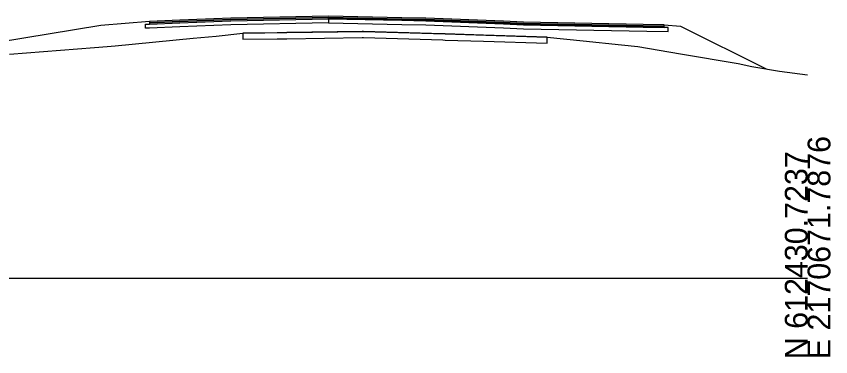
# Model space of a CAD drawing. Extents: x -26 to 1303, y -3010 to 12038.
# Drawn here: x 202.7 to 302.8, y 9490.3 to 9532.2 of the extents above; entities that cross this region are included whole.
import ezdxf

# ---------------------------------------------------------------- set-up
doc = ezdxf.new("R2010")
doc.units = 0
for name, color, linetype in [('RD_GPK_XS_Cell', 7, 'Continuous'), ('RD_XS_Base', 7, 'Continuous'), ('RD_XS_ExGround', 7, 'Continuous'), ('RD_XS_ExPaveRet', 7, 'Continuous'), ('RD_XS_Greenside', 7, 'Continuous'), ('RD_XS_Pave', 7, 'Continuous'), ('RD_XS_PaveOvlay_CP', 7, 'Continuous'), ('RD_XS_TieSlope', 7, 'Continuous')]:
    doc.layers.add(name, color=color, linetype=linetype)

msp = doc.modelspace()

# ---------------------------------------------------------------- linework, layer by layer
at = {"layer": 'RD_GPK_XS_Cell'}
msp.add_line((150, 9500), (300, 9500), dxfattribs=at)
at = {"layer": 'RD_XS_Base'}
for p, q in [((241.06, 9531.96), (241.06, 9532.07)), ((241.06, 9532.07), (241.06, 9531.59)), ((218.56, 9531.25), (218.75, 9531.26)), ((218.56, 9530.94), (218.56, 9531.25)), ((218.75, 9531.26), (219.06, 9531.27)), ((219.06, 9531.27), (222.79, 9531.42)), ((222.79, 9531.42), (229.06, 9531.67)), ((229.06, 9531.17), (222.79, 9530.92)), ((229.06, 9531.67), (241.06, 9531.91)), ((241.06, 9531.41), (229.06, 9531.17)), ((241.06, 9531.91), (241.06, 9531.96)), ((241.06, 9531.91), (241.06, 9531.91)), ((250.11, 9531.73), (241.06, 9531.91)), ((241.06, 9531.91), (241.06, 9531.91)), ((241.06, 9531.91), (241.06, 9531.55)), ((241.06, 9531.59), (241.06, 9531.41)), ((241.06, 9531.55), (241.06, 9531.41)), ((241.06, 9531.41), (250.11, 9531.23)), ((253.06, 9531.67), (250.11, 9531.73)), ((250.11, 9531.23), (253.06, 9531.17)), ((262.6, 9531.29), (253.06, 9531.67)), ((253.06, 9531.17), (262.6, 9530.79)), ((265.06, 9531.19), (262.6, 9531.29)), ((279.76, 9530.9), (265.06, 9531.19)), ((218.56, 9530.75), (218.56, 9530.94)), ((218.75, 9530.76), (218.56, 9530.75)), ((219.06, 9530.77), (218.75, 9530.76)), ((222.79, 9530.92), (219.06, 9530.77)), ((262.6, 9530.79), (265.06, 9530.69)), ((265.06, 9530.69), (280.21, 9530.39)), ((282.36, 9530.85), (279.76, 9530.9)), ((280.21, 9530.39), (282.86, 9530.34)), ((282.79, 9530.84), (282.36, 9530.85)), ((282.86, 9530.84), (282.79, 9530.84)), ((282.86, 9530.41), (282.86, 9530.84)), ((282.86, 9530.34), (282.86, 9530.41))]:
    msp.add_line(p, q, dxfattribs=at)
at = {"layer": 'RD_XS_ExGround'}
msp.add_lwpolyline([(201.83, 9527.58), (212.32, 9528.37), (213.87, 9528.49), (214.83, 9528.59), (224.44, 9529.53), (227.26, 9529.79), (230.55, 9530.14), (235.96, 9530.22), (245.39, 9530.36), (255.43, 9530.05), (267.97, 9529.67), (272.39, 9529.21), (277.13, 9528.7), (279.11, 9528.49), (284.36, 9527.59), (291.45, 9526.43), (293.12, 9526.03), (296.53, 9525.46), (300, 9525)], dxfattribs=at)
at = {"layer": 'RD_XS_ExPaveRet'}
for p, q in [((260.14, 9529.91), (255.43, 9530.05)), ((267.97, 9529.67), (260.14, 9529.91))]:
    msp.add_line(p, q, dxfattribs=at)
for points in [[(260.14, 9529.91), (255.43, 9530.05), (255.13, 9530.06), (245.39, 9530.36), (245.21, 9530.36), (235.96, 9530.22), (234.76, 9530.2), (230.55, 9530.14), (230.55, 9530.05), (230.55, 9529.39), (234.76, 9529.45), (235.96, 9529.47), (245.21, 9529.61), (245.39, 9529.61), (255.13, 9529.31), (255.43, 9529.3), (260.14, 9529.16), (267.97, 9528.92), (267.97, 9529.64), (267.97, 9529.67), (260.14, 9529.91)], [(235.96, 9530.22), (234.76, 9530.2), (230.55, 9530.14)], [(230.55, 9530.14), (230.55, 9530.05), (230.55, 9529.39), (234.76, 9529.45), (235.96, 9529.47), (245.21, 9529.61), (245.39, 9529.61), (255.13, 9529.31), (255.43, 9529.3), (260.14, 9529.16), (267.97, 9528.92), (267.97, 9529.64), (267.97, 9529.67)], [(255.43, 9530.05), (255.13, 9530.06), (245.39, 9530.36), (245.21, 9530.36), (235.96, 9530.22)]]:
    msp.add_lwpolyline(points, dxfattribs=at)
at = {"layer": 'RD_XS_Greenside'}
for p, q in [((213.06, 9531.11), (194.49, 9528.01)), ((284.36, 9531), (294.9, 9525.74))]:
    msp.add_line(p, q, dxfattribs=at)
at = {"layer": 'RD_XS_Pave'}
for p, q in [((229.06, 9531.99), (222.79, 9531.74)), ((241.06, 9532.23), (229.06, 9531.99)), ((241.06, 9532.07), (229.06, 9531.83)), ((229.06, 9531.83), (241.06, 9532.07)), ((250.11, 9532.05), (241.06, 9532.23)), ((241.06, 9531.96), (241.06, 9532.07)), ((241.06, 9532.07), (250.11, 9531.89)), ((250.11, 9531.89), (241.06, 9532.07)), ((241.06, 9532.07), (241.06, 9532.07)), ((241.06, 9532.07), (241.06, 9532.07)), ((241.06, 9532.07), (241.06, 9531.96)), ((253.06, 9531.99), (250.11, 9532.05)), ((262.6, 9531.61), (253.06, 9531.99)), ((222.79, 9531.74), (219.06, 9531.59)), ((219.06, 9531.59), (219.06, 9531.49)), ((222.79, 9531.58), (219.06, 9531.43)), ((219.06, 9531.43), (222.79, 9531.58)), ((219.06, 9531.49), (219.06, 9531.43)), ((219.06, 9531.43), (219.06, 9531.33)), ((219.06, 9531.27), (222.79, 9531.42)), ((219.06, 9531.33), (219.06, 9531.27)), ((229.06, 9531.83), (222.79, 9531.58)), ((222.79, 9531.58), (229.06, 9531.83)), ((222.79, 9531.42), (229.06, 9531.67)), ((229.06, 9531.67), (241.06, 9531.91)), ((241.06, 9531.91), (241.06, 9531.96)), ((241.06, 9531.96), (241.06, 9531.91)), ((241.06, 9531.91), (241.06, 9531.91)), ((241.06, 9531.91), (241.06, 9531.91)), ((241.06, 9531.91), (250.11, 9531.73)), ((250.11, 9531.89), (253.06, 9531.83)), ((253.06, 9531.83), (250.11, 9531.89)), ((250.11, 9531.73), (253.06, 9531.67)), ((253.06, 9531.83), (262.6, 9531.45)), ((262.6, 9531.45), (253.06, 9531.83)), ((253.06, 9531.67), (262.6, 9531.29)), ((265.06, 9531.51), (262.6, 9531.61)), ((262.6, 9531.45), (265.06, 9531.35)), ((265.06, 9531.35), (262.6, 9531.45)), ((262.6, 9531.29), (265.06, 9531.19)), ((279.76, 9531.22), (265.06, 9531.51)), ((265.06, 9531.35), (279.76, 9531.06)), ((279.76, 9531.06), (265.06, 9531.35)), ((265.06, 9531.19), (279.76, 9530.9)), ((282.36, 9531.16), (279.76, 9531.22)), ((279.76, 9531.06), (282.36, 9531)), ((282.36, 9531), (279.76, 9531.06)), ((282.36, 9531.03), (282.36, 9531.16)), ((282.36, 9531), (282.36, 9531.03)), ((282.36, 9530.87), (282.36, 9531)), ((279.76, 9530.9), (282.36, 9530.85)), ((282.36, 9530.85), (282.36, 9530.87))]:
    msp.add_line(p, q, dxfattribs=at)
at = {"layer": 'RD_XS_PaveOvlay_CP'}
for p, q in [((229.06, 9531.99), (222.79, 9531.74)), ((241.06, 9532.23), (229.06, 9531.99)), ((250.11, 9532.05), (241.06, 9532.23)), ((253.06, 9531.99), (250.11, 9532.05)), ((262.6, 9531.61), (253.06, 9531.99)), ((222.79, 9531.74), (219.06, 9531.59)), ((265.06, 9531.51), (262.6, 9531.61)), ((279.76, 9531.22), (265.06, 9531.51)), ((282.36, 9531.16), (279.76, 9531.22))]:
    msp.add_line(p, q, dxfattribs=at)
at = {"layer": 'RD_XS_TieSlope'}
for p, q in [((219.06, 9531.59), (213.06, 9531.11)), ((282.36, 9531.16), (284.36, 9531))]:
    msp.add_line(p, q, dxfattribs=at)

# ---------------------------------------------------------------- texts
at = {"layer": 'RD_GPK_XS_Cell'}
for s, p in [('E 2170671.7876', (302.8, 9490)), ('N 612430.7237', (300, 9490))]:
    msp.add_text(s, height=2.8, rotation=90, dxfattribs=at).set_placement(p)

doc.saveas('drawing.dxf')
